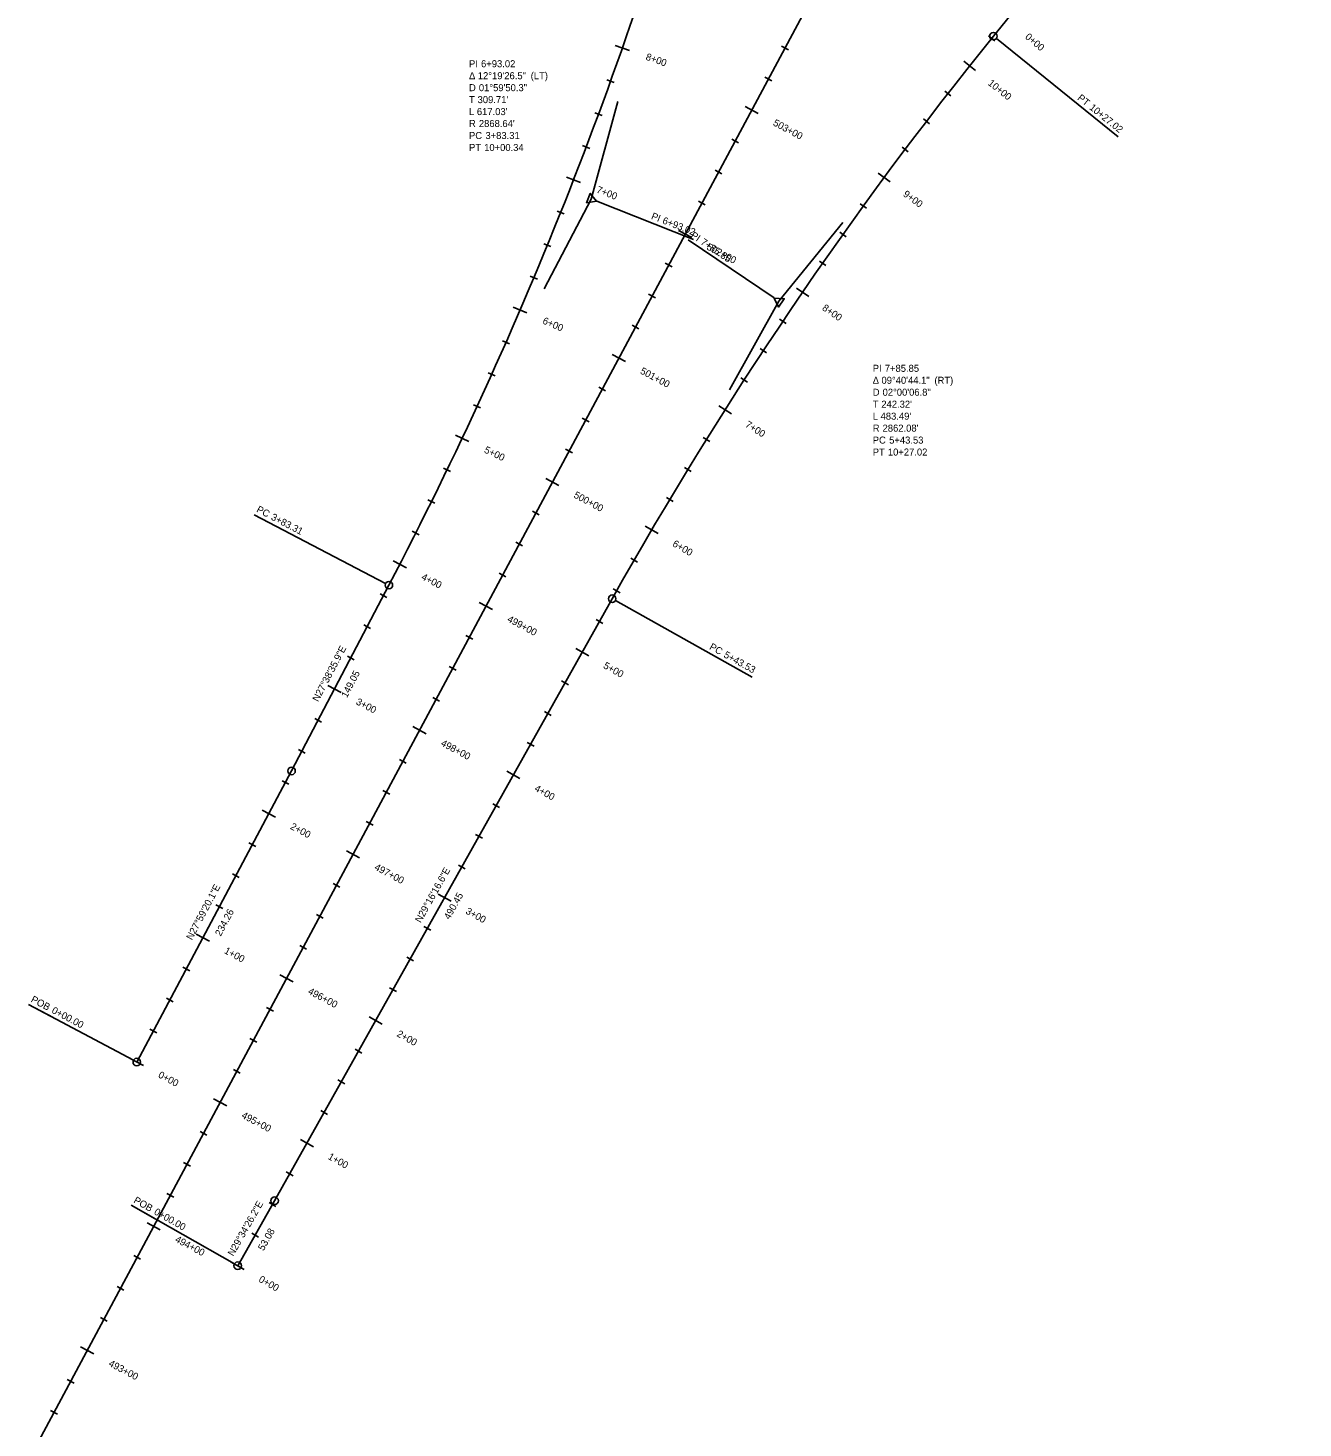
# Model space of a CAD drawing. Extents: x 2300830 to 2307917, y 756066 to 766359.
# Drawn here: x 2301986 to 2302891, y 758605 to 759600 of the extents above; entities that cross this region are included whole.
import ezdxf

# ---------------------------------------------------------------- set-up
doc = ezdxf.new("R2010")
doc.units = 0
for name, color, linetype in [('Default', 7, 'Continuous'), ('Draft_Bearing Label', 7, 'Continuous'), ('Draft_Curve Data Label', 7, 'Continuous'), ('Draft_Station Cardinal Lines', 7, 'Continuous'), ('Draft_Station Cardinal Points', 7, 'Continuous'), ('Draft_Station Labels Major', 7, 'Continuous'), ('Draft_Station Ticks Major', 7, 'Continuous'), ('Draft_Station Ticks Minor', 7, 'Continuous'), ('Geom_Baseline', 7, 'Continuous')]:
    doc.layers.add(name, color=color, linetype=linetype)

msp = doc.modelspace()

# ---------------------------------------------------------------- linework, layer by layer
at = {"layer": 'Default'}
for p, q in [((2301469.01, 757616.61), (2303797.09, 761964.97)), ((2301469.01, 757616.61), (2303797.09, 761964.97)), ((2302671.51, 759594.38), (2303742.71, 760919.55)), ((2302172.91, 759072.14), (2302242.06, 759204.18)), ((2302160.89, 758766.72), (2302400.69, 759194.55))]:
    msp.add_line(p, q, dxfattribs=at)
for centre, radius, start, end in [((2299700.87, 760535.13), 2868.64, 332.35668, 344.6807), ((2304897.33, 757795.14), 2862.08, 141.04981, 150.72872)]:
    msp.add_arc(centre, radius, start, end, dxfattribs=at)
at = {"layer": 'Draft_Station Cardinal Lines'}
for p, q in [((2302673.58, 759592.7), (2302760.16, 759522.71)), ((2302385.76, 759478.54), (2302404.78, 759547.98)), ((2302385.76, 759478.54), (2302352.35, 759414.75)), ((2302389.67, 759477), (2302458.34, 759449.97)), ((2302519.17, 759405.93), (2302564.43, 759461.92)), ((2302515.69, 759408.28), (2302454.59, 759449.67)), ((2302519.17, 759405.93), (2302483.97, 759343.12)), ((2302239.7, 759205.42), (2302146.39, 759254.29)), ((2302403.02, 759193.24), (2302500.13, 759138.81))]:
    msp.add_line(p, q, dxfattribs=at)
for points in [[(2302389.63, 759477.01), (2302385.14, 759482.65), (2302382.51, 759475.95)], [(2302515.73, 759408.26), (2302518.87, 759401.78), (2302522.91, 759407.74)]]:
    msp.add_lwpolyline(points, close=True, dxfattribs=at)
at = {"layer": 'Draft_Station Cardinal Points'}
for p, q in [((2302671.51, 759594.38), (2302671.51, 759594.38)), ((2302760.16, 759522.71), (2302760.16, 759522.71)), ((2302385.76, 759478.54), (2302385.76, 759478.54)), ((2302454.59, 759449.67), (2302454.59, 759449.67)), ((2302458.34, 759449.97), (2302458.34, 759449.97)), ((2302519.17, 759405.93), (2302519.17, 759405.93)), ((2302146.39, 759254.29), (2302146.39, 759254.29)), ((2302242.06, 759204.18), (2302242.06, 759204.18)), ((2302400.69, 759194.55), (2302400.69, 759194.55)), ((2302500.13, 759138.81), (2302500.13, 759138.81)), ((2302172.91, 759072.14), (2302172.91, 759072.14)), ((2302060.61, 758866.53), (2301986.15, 758906.11)), ((2301986.15, 758906.11), (2302003.53, 758896.87)), ((2302062.97, 758865.28), (2302062.97, 758865.28)), ((2302132.37, 758721.87), (2302059.02, 758763.49)), ((2302059.02, 758763.49), (2302076.14, 758753.78)), ((2302160.89, 758766.72), (2302160.89, 758766.72)), ((2302134.69, 758720.56), (2302134.69, 758720.56))]:
    msp.add_line(p, q, dxfattribs=at)
for centre in [(2302671.51, 759594.38), (2302242.06, 759204.18), (2302400.69, 759194.55), (2302172.91, 759072.14), (2302062.97, 758865.28), (2302160.89, 758766.72), (2302134.69, 758720.56)]:
    msp.add_circle(centre, 2.67, dxfattribs=at)
at = {"layer": 'Draft_Station Ticks Major'}
for p, q in [((2302402.91, 759587.79), (2302412.94, 759584.28)), ((2302650.44, 759576.6), (2302658.76, 759570.01)), ((2302495.1, 759544.44), (2302504.46, 759539.43)), ((2302589.58, 759497.03), (2302598.12, 759490.72)), ((2302368.25, 759494.19), (2302378.15, 759490.33)), ((2302447.9, 759456.28), (2302457.26, 759451.27)), ((2302531.53, 759415.37), (2302540.3, 759409.37)), ((2302330.35, 759401.86), (2302340.11, 759397.66)), ((2302400.7, 759368.12), (2302410.06, 759363.11)), ((2302476.38, 759331.74), (2302485.35, 759326.05)), ((2302289.26, 759310.9), (2302298.86, 759306.36)), ((2302353.5, 759279.96), (2302362.86, 759274.95)), ((2302424.18, 759246.23), (2302433.34, 759240.86)), ((2302245.02, 759221.44), (2302254.46, 759216.56)), ((2302306.3, 759191.8), (2302315.66, 759186.79)), ((2302374.75, 759159.19), (2302384.01, 759153.99)), ((2302198.68, 759132.86), (2302208.09, 759127.93)), ((2302259.1, 759103.64), (2302268.46, 759098.63)), ((2302325.85, 759071.95), (2302335.12, 759066.76)), ((2302152.12, 759044.39), (2302161.49, 759039.41)), ((2302211.9, 759015.48), (2302221.26, 759010.47)), ((2302276.96, 758984.72), (2302286.22, 758979.53)), ((2302105.19, 758956.09), (2302114.56, 758951.11)), ((2302164.7, 758927.32), (2302174.06, 758922.31)), ((2302228.06, 758897.49), (2302237.33, 758892.3)), ((2302058.26, 758867.79), (2302067.63, 758862.8)), ((2302117.5, 758839.16), (2302126.86, 758834.15)), ((2302179.17, 758810.26), (2302188.43, 758805.07)), ((2302070.3, 758751), (2302079.66, 758745.99)), ((2302130.05, 758723.19), (2302139.28, 758717.95)), ((2302023.1, 758662.84), (2302032.46, 758657.83))]:
    msp.add_line(p, q, dxfattribs=at)
at = {"layer": 'Draft_Station Ticks Minor'}
for p, q in [((2302520.98, 759587.3), (2302525.84, 759584.7)), ((2302668.09, 759594.54), (2302672.39, 759591.07)), ((2302396.98, 759563.4), (2302402.18, 759561.53)), ((2302509.18, 759565.26), (2302514.04, 759562.66)), ((2302637, 759555.32), (2302641.35, 759551.93)), ((2302388.41, 759539.94), (2302393.59, 759538.03)), ((2302621.71, 759535.51), (2302626.09, 759532.16)), ((2302379.64, 759516.56), (2302384.8, 759514.6)), ((2302485.58, 759521.18), (2302490.44, 759518.58)), ((2302606.59, 759515.57), (2302611.01, 759512.26)), ((2302473.78, 759499.14), (2302478.64, 759496.54)), ((2302461.98, 759477.1), (2302466.84, 759474.5)), ((2302361.48, 759470.03), (2302366.6, 759467.98)), ((2302576.89, 759475.29), (2302581.36, 759472.05)), ((2302352.09, 759446.88), (2302357.2, 759444.79)), ((2302562.3, 759454.96), (2302566.8, 759451.76)), ((2302438.38, 759433.02), (2302443.24, 759430.42)), ((2302547.89, 759434.5), (2302552.42, 759431.34)), ((2302342.51, 759423.82), (2302347.6, 759421.68)), ((2302426.58, 759410.98), (2302431.44, 759408.38)), ((2302414.78, 759388.94), (2302419.64, 759386.34)), ((2302519.61, 759393.21), (2302524.19, 759390.13)), ((2302322.74, 759377.95), (2302327.79, 759375.72)), ((2302505.75, 759372.38), (2302510.35, 759369.34)), ((2302312.55, 759355.14), (2302317.59, 759352.87)), ((2302492.06, 759351.43), (2302496.69, 759348.43)), ((2302391.18, 759344.86), (2302396.04, 759342.26)), ((2302302.17, 759332.43), (2302307.18, 759330.11)), ((2302379.38, 759322.82), (2302384.24, 759320.22)), ((2302465.24, 759309.17), (2302469.93, 759306.25)), ((2302367.58, 759300.78), (2302372.44, 759298.18)), ((2302280.82, 759287.27), (2302285.78, 759284.87)), ((2302452.11, 759287.87), (2302456.82, 759284.99)), ((2302269.84, 759264.83), (2302274.79, 759262.39)), ((2302439.16, 759266.46), (2302443.9, 759263.62)), ((2302343.98, 759256.7), (2302348.84, 759254.1)), ((2302258.67, 759242.49), (2302263.6, 759240)), ((2302332.18, 759234.66), (2302337.04, 759232.06)), ((2302413.84, 759223.29), (2302418.62, 759220.54)), ((2302320.38, 759212.62), (2302325.24, 759210.02)), ((2302235.76, 759198.1), (2302240.65, 759195.54)), ((2302401.46, 759201.54), (2302406.26, 759198.83)), ((2302389.22, 759179.73), (2302394.04, 759177.03)), ((2302224.16, 759175.95), (2302229.05, 759173.39)), ((2302296.78, 759168.54), (2302301.64, 759165.94)), ((2302212.57, 759153.8), (2302217.46, 759151.24)), ((2302284.98, 759146.5), (2302289.84, 759143.9)), ((2302364.78, 759136.12), (2302369.59, 759133.42)), ((2302273.18, 759124.46), (2302278.04, 759121.86)), ((2302189.37, 759109.51), (2302194.26, 759106.95)), ((2302352.55, 759114.31), (2302357.37, 759111.61)), ((2302340.33, 759092.5), (2302345.14, 759089.8)), ((2302177.77, 759087.37), (2302182.66, 759084.8)), ((2302249.58, 759080.38), (2302254.44, 759077.78)), ((2302166.13, 759065.26), (2302171, 759062.67)), ((2302237.78, 759058.34), (2302242.64, 759055.74)), ((2302315.88, 759048.89), (2302320.7, 759046.19)), ((2302225.98, 759036.3), (2302230.84, 759033.7)), ((2302142.66, 759021.11), (2302147.54, 759018.52)), ((2302303.66, 759027.08), (2302308.47, 759024.38)), ((2302130.93, 758999.03), (2302135.8, 758996.44)), ((2302291.43, 759005.27), (2302296.25, 759002.57)), ((2302202.38, 758992.22), (2302207.24, 758989.62)), ((2302119.2, 758976.96), (2302124.07, 758974.37)), ((2302190.58, 758970.18), (2302195.44, 758967.58)), ((2302266.99, 758961.65), (2302271.8, 758958.95)), ((2302178.78, 758948.14), (2302183.64, 758945.54)), ((2302254.76, 758939.85), (2302259.58, 758937.15)), ((2302095.73, 758932.8), (2302100.61, 758930.21)), ((2302084, 758910.73), (2302088.87, 758908.14)), ((2302242.54, 758918.04), (2302247.35, 758915.34)), ((2302155.18, 758904.06), (2302160.04, 758901.46)), ((2302072.27, 758888.65), (2302077.14, 758886.06)), ((2302143.38, 758882.02), (2302148.24, 758879.42)), ((2302218.09, 758874.42), (2302222.91, 758871.72)), ((2302131.58, 758859.98), (2302136.44, 758857.38)), ((2302205.87, 758852.61), (2302210.68, 758849.92)), ((2302193.64, 758830.81), (2302198.46, 758828.11)), ((2302107.97, 758815.9), (2302112.84, 758813.3)), ((2302096.17, 758793.86), (2302101.04, 758791.26)), ((2302169.2, 758787.19), (2302174.01, 758784.49)), ((2302084.37, 758771.82), (2302089.24, 758769.22)), ((2302156.97, 758765.4), (2302161.77, 758762.68)), ((2302144.63, 758743.66), (2302149.43, 758740.94)), ((2302060.77, 758727.74), (2302065.64, 758725.14)), ((2302048.97, 758705.7), (2302053.84, 758703.1)), ((2302037.17, 758683.66), (2302042.04, 758681.06)), ((2302013.57, 758639.58), (2302018.44, 758636.98)), ((2302001.77, 758617.55), (2302006.64, 758614.94))]:
    msp.add_line(p, q, dxfattribs=at)
at = {"layer": 'Geom_Baseline'}
for p, q in [((2301469.01, 757616.61), (2303797.09, 761964.97)), ((2302671.51, 759594.38), (2303742.71, 760919.55)), ((2302172.91, 759072.14), (2302242.06, 759204.18)), ((2302160.89, 758766.72), (2302400.69, 759194.55)), ((2302062.97, 758865.28), (2302172.91, 759072.14)), ((2302134.69, 758720.56), (2302160.89, 758766.72))]:
    msp.add_line(p, q, dxfattribs=at)
for centre, radius, start, end in [((2299700.87, 760535.13), 2868.64, 332.35668, 344.6807), ((2304897.33, 757795.14), 2862.08, 141.04981, 150.72872)]:
    msp.add_arc(centre, radius, start, end, dxfattribs=at)

# ---------------------------------------------------------------- texts
at = {"layer": 'Draft_Bearing Label'}
for s, rotation, p in [('N27°38\'35.9"E', 62.35668, (2302191.82, 759120.93)), ('149.05', 62.35668, (2302212.23, 759123.77)), ('N29°16\'16.6"E', 60.72872, (2302264.64, 758963.85)), ('N27°59\'20.1"E', 62.01108, (2302102.17, 758951.57)), ('490.45', 60.72872, (2302285.13, 758966.12)), ('234.26', 62.01108, (2302122.61, 758954.31)), ('N29°34\'26.2"E', 60.42606, (2302131.55, 758726.94)), ('53.08', 60.42606, (2302153.02, 758730.8))]:
    msp.add_text(s, height=5, rotation=rotation, dxfattribs=at).set_placement(p)
at = {"layer": 'Draft_Curve Data Label'}
for s, p in [('PI ', (2302298.99, 759572.26)), ('6+93.02', (2302307.53, 759572.26)), ('Δ ', (2302298.99, 759563.76)), ('12°19\'26.5"', (2302305.21, 759563.76)), (' (LT)', (2302340.94, 759563.76)), ('D ', (2302298.99, 759555.26)), ('01°59\'50.3"', (2302305.98, 759555.26)), ('T ', (2302298.99, 759546.76)), ("309.71'", (2302305.07, 759546.76)), ('L ', (2302298.99, 759538.26)), ("617.03'", (2302304.56, 759538.26)), ('R ', (2302298.99, 759529.76)), ('PC ', (2302298.99, 759521.26)), ("2868.64'", (2302305.98, 759529.76)), ('3+83.31', (2302310.64, 759521.26)), ('PT ', (2302298.99, 759512.76)), ('10+00.34', (2302309.73, 759512.76)), ('PI ', (2302585.77, 759355.81)), ('7+85.85', (2302594.32, 759355.81)), ('Δ ', (2302585.77, 759347.31)), ('09°40\'44.1"', (2302591.99, 759347.31)), (' (RT)', (2302627.73, 759347.31)), ('D ', (2302585.77, 759338.81)), ('02°00\'06.8"', (2302592.76, 759338.81)), ('T ', (2302585.77, 759330.31)), ("483.49'", (2302591.34, 759321.81)), ("242.32'", (2302591.86, 759330.31)), ('L ', (2302585.77, 759321.81)), ('R ', (2302585.77, 759313.31)), ("2862.08'", (2302592.76, 759313.31)), ('PC ', (2302585.77, 759304.81)), ('5+43.53', (2302597.42, 759304.81)), ('PT ', (2302585.77, 759296.31)), ('10+27.02', (2302596.52, 759296.31))]:
    msp.add_text(s, height=5, dxfattribs=at).set_placement(p)
at = {"layer": 'Draft_Station Cardinal Points'}
for s, rotation, p in [('PT', 321.04981, (2302730.76, 759549.67)), ('10+27.02', 321.04981, (2302739.21, 759542.84)), ('PI ', 338.51869, (2302427.98, 759464.59)), ('6+93.02', 338.51869, (2302435.93, 759461.46)), ('PI ', 325.88926, (2302455.98, 759451.72)), ('7+85.85', 325.88926, (2302463.05, 759446.93)), ('PC', 332.35668, (2302147.54, 759256.49)), ('3+83.31', 332.35668, (2302157.86, 759251.08)), ('PC', 330.72872, (2302469.28, 759158.95)), ('5+43.53', 330.72872, (2302479.44, 759153.25)), ('POB ', 332.01108, (2301987.31, 758908.3)), ('0+00.00', 332.01108, (2302002.06, 758900.47)), ('POB ', 330.42606, (2302060.25, 758765.65)), ('0+00.00', 330.42606, (2302074.77, 758757.41))]:
    msp.add_text(s, height=5, rotation=rotation, dxfattribs=at).set_placement(p)
at = {"layer": 'Draft_Station Labels Major'}
for s, rotation, p in [('0+00', 319.75294, (2302693.58, 759593.15)), ('8+00', 340.6793, (2302424.11, 759577.71)), ('10+00', 321.59067, (2302667.17, 759560.14)), ('503+00', 331.8357, (2302514.5, 759531.22)), ('7+00', 338.68198, (2302389.09, 759483.38)), ('9+00', 323.59256, (2302606.88, 759481.16)), ('502+00', 331.8357, (2302467.3, 759443.06)), ('8+00', 325.59445, (2302549.38, 759400.12)), ('6+00', 336.68467, (2302350.8, 759390.33)), ('501+00', 331.8357, (2302420.1, 759354.9)), ('7+00', 327.59634, (2302494.75, 759317.12)), ('5+00', 334.68736, (2302309.29, 759298.66)), ('500+00', 331.8357, (2302372.9, 759266.74)), ('6+00', 329.59823, (2302443.05, 759232.27)), ('4+00', 332.69004, (2302264.61, 759208.51)), ('499+00', 331.8357, (2302325.7, 759178.58)), ('5+00', 330.72872, (2302393.89, 759145.59)), ('3+00', 332.35668, (2302218.2, 759119.81)), ('498+00', 331.8357, (2302278.5, 759090.42)), ('4+00', 330.72872, (2302344.99, 759058.36)), ('2+00', 332.01108, (2302171.55, 759031.23)), ('497+00', 331.8357, (2302231.3, 759002.26)), ('3+00', 330.72872, (2302296.1, 758971.13)), ('1+00', 332.01108, (2302124.62, 758942.93)), ('496+00', 331.8357, (2302184.1, 758914.1)), ('2+00', 330.72872, (2302247.2, 758883.9)), ('0+00', 332.01108, (2302077.69, 758854.63)), ('495+00', 331.8357, (2302136.9, 758825.94)), ('1+00', 330.72872, (2302198.31, 758796.67)), ('494+00', 331.8357, (2302089.7, 758737.78)), ('0+00', 330.42606, (2302149.11, 758709.5)), ('493+00', 331.8357, (2302042.5, 758649.62))]:
    msp.add_text(s, height=5, rotation=rotation, dxfattribs=at).set_placement(p)

doc.saveas('drawing.dxf')
